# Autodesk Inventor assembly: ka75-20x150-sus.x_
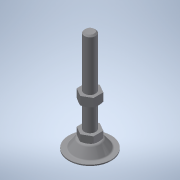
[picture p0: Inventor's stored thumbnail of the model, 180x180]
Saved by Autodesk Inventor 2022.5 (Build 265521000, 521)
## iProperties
Part Number: ka75-20x150-sus.x_
Material: 一般
Document SubType Name: Assembly
Designer: ImaoCorp
Sending System: SOLIDWORKS 2017-2017317
MC: AMD64
MC_MODEL: Intel64 Family 6 Model 60 Stepping 3, GenuineIntel
OS: Windows_NT
FRU: Parasolid Version 29.0, build 201,  4-17-2017
FORMAT: text
GUISE: transmit
KEY: ka75-20x150-sus
FILE: ka75-20x150-sus.x_t
DATE: Mon Jul 01 17:42:31 2019
Author: ImaoCorp
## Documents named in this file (3)
- X:\14_SW2022-Inv2022\00_全2023-1023新製品(TCC)まで\k\ka75-20x150-sus\KA75-20X150-SUS.iam
- X:\14_SW2022-Inv2022\00_全2023-1023新製品(TCC)まで\k\ka75-20x150-sus\ka75-20x150-sus_01.ipt
- X:\14_SW2022-Inv2022\00_全2023-1023新製品(TCC)まで\k\ka75-20x150-sus\ka75-20x150-sus_02.ipt
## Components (2 placed, 2 different names)
1. ka75-20x150-sus_01
2. ka75-20x150-sus_02
